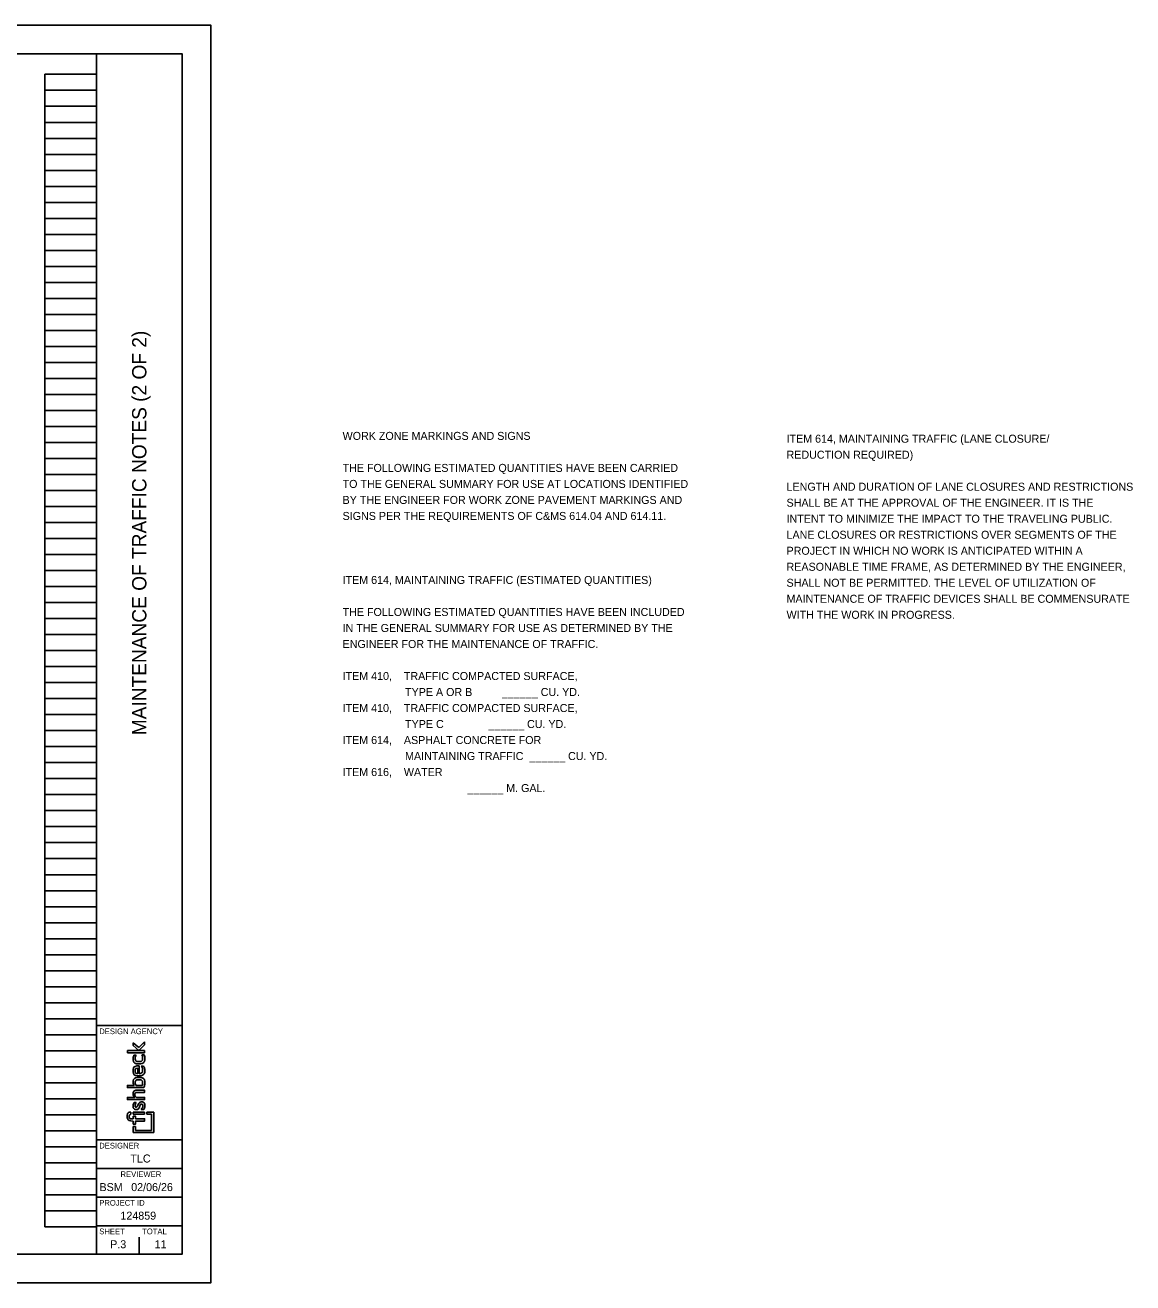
# Model space of a CAD drawing. Extents: x 0 to 50.1, y 0 to 22.
# Drawn here: x 30.75 to 50.13, y 0 to 22 of the extents above; entities that cross this region are included whole.
import ezdxf

# ---------------------------------------------------------------- set-up
doc = ezdxf.new("R2010")
doc.units = 0
for name, color, linetype in [('SH_Border', 7, 'Continuous'), ('SH_Cut_Line', 7, 'Continuous'), ('SH_Data', 7, 'Continuous'), ('SH_Text', 7, 'Continuous')]:
    doc.layers.add(name, color=color, linetype=linetype)

msp = doc.modelspace()

# ---------------------------------------------------------------- linework, layer by layer
at = {"layer": 'SH_Border'}
for p, q in [((32, 0.5), (32, 21.5)), ((32, 4.5), (33.5, 4.5)), ((32, 2.5), (33.5, 2.5)), ((32, 2), (33.5, 2)), ((32, 1.5), (33.5, 1.5)), ((32, 1), (33.5, 1))]:
    msp.add_line(p, q, dxfattribs=at)
msp.add_lwpolyline([(1.5, 21.5), (33.5, 21.5), (33.5, 0.5), (1.5, 0.5)], close=True, dxfattribs=at)
at = {"layer": 'SH_Cut_Line'}
msp.add_lwpolyline([(0, 0), (34, 0), (34, 22), (0, 22)], close=True, dxfattribs=at)
at = {"layer": 'SH_Data'}
for p, q in [((31.1, 0.98), (31.1, 21.14)), ((31.1, 21.14), (32, 21.14)), ((32, 0.98), (32, 21.14)), ((31.1, 20.86), (32, 20.86)), ((31.1, 20.58), (32, 20.58)), ((31.1, 20.3), (32, 20.3)), ((31.1, 20.02), (32, 20.02)), ((31.1, 19.74), (32, 19.74)), ((31.1, 19.46), (32, 19.46)), ((31.1, 19.18), (32, 19.18)), ((31.1, 18.9), (32, 18.9)), ((31.1, 18.62), (32, 18.62)), ((31.1, 18.34), (32, 18.34)), ((31.1, 18.06), (32, 18.06)), ((31.1, 17.78), (32, 17.78)), ((31.1, 17.5), (32, 17.5)), ((31.1, 17.22), (32, 17.22)), ((31.1, 16.94), (32, 16.94)), ((31.1, 16.66), (32, 16.66)), ((31.1, 16.38), (32, 16.38)), ((31.1, 16.1), (32, 16.1)), ((31.1, 15.82), (32, 15.82)), ((31.1, 15.54), (32, 15.54)), ((31.1, 15.26), (32, 15.26)), ((31.1, 14.98), (32, 14.98)), ((31.1, 14.7), (32, 14.7)), ((31.1, 14.42), (32, 14.42)), ((31.1, 14.14), (32, 14.14)), ((31.1, 13.86), (32, 13.86)), ((31.1, 13.58), (32, 13.58)), ((31.1, 13.3), (32, 13.3)), ((31.1, 13.02), (32, 13.02)), ((31.1, 12.74), (32, 12.74)), ((31.1, 12.46), (32, 12.46)), ((31.1, 12.18), (32, 12.18)), ((31.1, 11.9), (32, 11.9)), ((31.1, 11.62), (32, 11.62)), ((31.1, 11.34), (32, 11.34)), ((31.1, 11.06), (32, 11.06)), ((31.1, 10.78), (32, 10.78)), ((31.1, 10.5), (32, 10.5)), ((31.1, 10.22), (32, 10.22)), ((31.1, 9.94), (32, 9.94)), ((31.1, 9.66), (32, 9.66)), ((31.1, 9.38), (32, 9.38)), ((31.1, 9.1), (32, 9.1)), ((31.1, 8.82), (32, 8.82)), ((31.1, 8.54), (32, 8.54)), ((31.1, 8.26), (32, 8.26)), ((31.1, 7.98), (32, 7.98)), ((31.1, 7.7), (32, 7.7)), ((31.1, 7.42), (32, 7.42)), ((31.1, 7.14), (32, 7.14)), ((31.1, 6.86), (32, 6.86)), ((31.1, 6.58), (32, 6.58)), ((31.1, 6.3), (32, 6.3)), ((31.1, 6.02), (32, 6.02)), ((31.1, 5.74), (32, 5.74)), ((31.1, 5.46), (32, 5.46)), ((31.1, 5.18), (32, 5.18)), ((31.1, 4.9), (32, 4.9)), ((31.1, 4.62), (32, 4.62)), ((31.1, 4.34), (32, 4.34)), ((32.646, 4.198), (32.646, 4.151)), ((32.742, 4.114), (32.646, 4.198)), ((32.842, 4.215), (32.742, 4.114)), ((32.842, 4.163), (32.842, 4.215)), ((31.1, 4.06), (32, 4.06)), ((32.544, 4.063), (32.544, 4.024)), ((32.842, 4.063), (32.544, 4.063)), ((32.544, 4.024), (32.842, 4.024)), ((32.646, 4.151), (32.742, 4.065)), ((32.697, 3.983), (32.656, 3.983)), ((32.742, 4.065), (32.842, 4.163)), ((32.835, 3.987), (32.796, 3.987)), ((32.842, 4.024), (32.842, 4.063)), ((31.1, 3.78), (32, 3.78)), ((32.724, 3.758), (32.724, 3.66)), ((32.75, 3.659), (32.75, 3.797)), ((32.823, 3.793), (32.785, 3.793)), ((31.1, 3.5), (32, 3.5)), ((32.803, 3.454), (32.697, 3.454)), ((32.75, 3.5), (32.75, 3.5)), ((31.1, 3.22), (32, 3.22)), ((32.697, 3.156), (32.658, 3.156)), ((31.1, 2.94), (32, 2.94)), ((32.603, 2.948), (32.603, 2.987)), ((32.646, 2.987), (32.646, 2.948)), ((32.842, 2.987), (32.646, 2.987)), ((32.646, 2.948), (32.842, 2.948)), ((32.786, 3.032), (32.828, 3.032)), ((32.842, 2.948), (32.842, 2.987)), ((33.005, 2.987), (32.885, 2.987)), ((32.885, 2.987), (32.885, 2.948)), ((32.885, 2.948), (32.966, 2.948)), ((32.966, 2.948), (32.966, 2.667)), ((33.005, 2.628), (33.005, 2.987)), ((31.1, 2.66), (32, 2.66)), ((32.685, 2.734), (32.646, 2.734)), ((32.646, 2.734), (32.646, 2.628)), ((32.685, 2.667), (32.685, 2.734)), ((32.966, 2.667), (32.685, 2.667)), ((32.646, 2.628), (33.005, 2.628)), ((31.1, 2.38), (32, 2.38)), ((31.1, 2.1), (32, 2.1)), ((31.1, 1.82), (32, 1.82)), ((31.1, 1.54), (32, 1.54)), ((31.1, 1.26), (32, 1.26)), ((31.1, 0.98), (32, 0.98)), ((32.375, 0.675), (32.375, 0.675)), ((32.75, 0.5), (32.75, 0.8))]:
    msp.add_line(p, q, dxfattribs=at)
for points in [[(32.66, 3.454), (32.544, 3.454), (32.544, 3.415), (32.831, 3.415)], [(32.721, 3.332), (32.842, 3.332), (32.842, 3.37), (32.722, 3.37)], [(32.672, 3.245), (32.672, 3.244), (32.544, 3.244), (32.544, 3.205), (32.842, 3.205), (32.842, 3.244), (32.701, 3.244)], [(32.646, 2.831), (32.646, 2.778), (32.685, 2.778), (32.685, 2.831), (32.842, 2.831), (32.842, 2.869), (32.685, 2.869), (32.685, 2.913), (32.646, 2.913), (32.646, 2.869)]]:
    msp.add_lwpolyline(points, dxfattribs=at)
for points in [[(32.656, 3.983), (32.647, 3.964), (32.642, 3.949), (32.642, 3.926), (32.642, 3.867), (32.683, 3.829), (32.748, 3.829), (32.805, 3.829), (32.846, 3.87), (32.846, 3.929), (32.846, 3.949), (32.841, 3.974), (32.835, 3.987)], [(32.796, 3.987), (32.805, 3.968), (32.809, 3.952), (32.809, 3.935), (32.809, 3.895), (32.785, 3.869), (32.744, 3.869), (32.705, 3.869), (32.678, 3.894), (32.678, 3.929), (32.678, 3.946), (32.682, 3.961), (32.697, 3.983)], [(32.75, 3.797), (32.677, 3.797), (32.642, 3.764), (32.642, 3.712), (32.642, 3.658), (32.682, 3.62), (32.742, 3.62), (32.796, 3.62), (32.846, 3.654), (32.846, 3.715), (32.846, 3.748), (32.839, 3.77), (32.823, 3.793)], [(32.724, 3.66), (32.693, 3.665), (32.676, 3.683), (32.676, 3.713), (32.676, 3.74), (32.695, 3.757), (32.724, 3.758)], [(32.785, 3.793), (32.8, 3.771), (32.809, 3.748), (32.809, 3.725), (32.809, 3.687), (32.789, 3.665), (32.75, 3.659)], [(32.831, 3.415), (32.84, 3.435), (32.846, 3.462), (32.846, 3.488), (32.846, 3.554), (32.806, 3.593), (32.74, 3.593), (32.684, 3.593), (32.642, 3.557), (32.642, 3.508), (32.642, 3.489), (32.648, 3.471), (32.66, 3.454)], [(32.697, 3.454), (32.682, 3.471), (32.677, 3.483), (32.677, 3.499), (32.677, 3.531), (32.704, 3.553), (32.746, 3.553), (32.783, 3.553), (32.809, 3.528), (32.809, 3.493), (32.809, 3.482), (32.807, 3.466), (32.803, 3.454)], [(32.722, 3.37), (32.668, 3.37), (32.642, 3.342), (32.642, 3.304), (32.642, 3.282), (32.653, 3.26), (32.672, 3.245)], [(32.701, 3.244), (32.681, 3.263), (32.673, 3.276), (32.673, 3.293), (32.673, 3.317), (32.692, 3.332), (32.721, 3.332)], [(32.658, 3.156), (32.647, 3.135), (32.642, 3.116), (32.642, 3.098), (32.642, 3.059), (32.662, 3.033), (32.695, 3.033), (32.748, 3.033), (32.763, 3.125), (32.79, 3.125), (32.804, 3.125), (32.811, 3.112), (32.812, 3.096), (32.812, 3.08), (32.804, 3.057), (32.786, 3.032)], [(32.828, 3.032), (32.841, 3.057), (32.846, 3.076), (32.846, 3.1), (32.846, 3.137), (32.823, 3.165), (32.788, 3.165), (32.768, 3.165), (32.755, 3.153), (32.733, 3.121), (32.713, 3.086), (32.703, 3.073), (32.694, 3.073), (32.684, 3.073), (32.676, 3.083), (32.676, 3.099), (32.676, 3.113), (32.682, 3.134), (32.697, 3.156)], [(32.603, 2.987), (32.565, 2.986), (32.54, 2.957), (32.54, 2.914), (32.54, 2.86), (32.574, 2.829), (32.646, 2.831)], [(32.646, 2.869), (32.598, 2.866), (32.575, 2.882), (32.575, 2.913), (32.575, 2.931), (32.584, 2.941), (32.603, 2.948)]]:
    msp.add_open_spline(points, degree=3, dxfattribs=at)

# ---------------------------------------------------------------- texts
msp.add_text('MAINTENANCE OF TRAFFIC NOTES (2 OF 2)', height=0.25, rotation=90, dxfattribs=at).set_placement((32.875, 9.579))
for s, height, p in [('DESIGN AGENCY', 0.1, (32.05, 4.35)), ('DESIGNER', 0.1, (32.05, 2.35)), ('TLC', 0.14, (32.595, 2.105)), ('REVIEWER', 0.1, (32.422, 1.85)), ('BSM', 0.14, (32.054, 1.605)), ('02/06/26', 0.14, (32.609, 1.605)), ('PROJECT ID', 0.1, (32.05, 1.35)), ('124859', 0.14, (32.42, 1.105)), ('SHEET', 0.1, (32.05, 0.85)), ('TOTAL', 0.1, (32.8, 0.85)), ('P.3', 0.14, (32.241, 0.605)), ('11', 0.14, (33.019, 0.605))]:
    msp.add_text(s, height=height, dxfattribs=at).set_placement(p)
at = {"layer": 'SH_Text'}
for s, p in [('WORK ZONE MARKINGS AND SIGNS', (36.306, 14.745)), ('ITEM 614, MAINTAINING TRAFFIC (LANE CLOSURE/', (44.07, 14.696)), ('REDUCTION REQUIRED)', (44.07, 14.416)), ('THE FOLLOWING ESTIMATED QUANTITIES HAVE BEEN CARRIED', (36.306, 14.185)), ('TO THE GENERAL SUMMARY FOR USE AT LOCATIONS IDENTIFIED', (36.306, 13.905)), ('LENGTH AND DURATION OF LANE CLOSURES AND RESTRICTIONS', (44.07, 13.856)), ('BY THE ENGINEER FOR WORK ZONE PAVEMENT MARKINGS AND', (36.306, 13.625)), ('SHALL BE AT THE APPROVAL OF THE ENGINEER. IT IS THE', (44.07, 13.576)), ('SIGNS PER THE REQUIREMENTS OF C&MS 614.04 AND 614.11.', (36.306, 13.345)), ('INTENT TO MINIMIZE THE IMPACT TO THE TRAVELING PUBLIC.', (44.07, 13.296)), ('LANE CLOSURES OR RESTRICTIONS OVER SEGMENTS OF THE', (44.07, 13.016)), ('PROJECT IN WHICH NO WORK IS ANTICIPATED WITHIN A', (44.07, 12.736)), ('REASONABLE TIME FRAME, AS DETERMINED BY THE ENGINEER,', (44.07, 12.456)), ('ITEM 614, MAINTAINING TRAFFIC (ESTIMATED QUANTITIES)', (36.306, 12.225)), ('SHALL NOT BE PERMITTED. THE LEVEL OF UTILIZATION OF', (44.07, 12.176)), ('MAINTENANCE OF TRAFFIC DEVICES SHALL BE COMMENSURATE', (44.07, 11.896)), ('THE FOLLOWING ESTIMATED QUANTITIES HAVE BEEN INCLUDED', (36.306, 11.665)), ('WITH THE WORK IN PROGRESS.', (44.07, 11.616)), ('IN THE GENERAL SUMMARY FOR USE AS DETERMINED BY THE', (36.306, 11.385)), ('ENGINEER FOR THE MAINTENANCE OF TRAFFIC.', (36.306, 11.105)), ('ITEM 410,    TRAFFIC COMPACTED SURFACE,', (36.306, 10.545)), ('                     TYPE A OR B          ______ CU. YD.', (36.306, 10.265)), ('ITEM 410,    TRAFFIC COMPACTED SURFACE,', (36.306, 9.985)), ('                     TYPE C               ______ CU. YD.', (36.306, 9.705)), ('ITEM 614,    ASPHALT CONCRETE FOR', (36.306, 9.425)), ('                     MAINTAINING TRAFFIC  ______ CU. YD.', (36.306, 9.145)), ('ITEM 616,    WATER', (36.306, 8.865)), ('                                          ______ M. GAL.', (36.306, 8.585))]:
    msp.add_text(s, height=0.14, dxfattribs=at).set_placement(p)

doc.saveas('drawing.dxf')
